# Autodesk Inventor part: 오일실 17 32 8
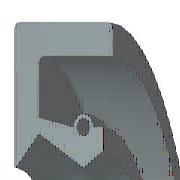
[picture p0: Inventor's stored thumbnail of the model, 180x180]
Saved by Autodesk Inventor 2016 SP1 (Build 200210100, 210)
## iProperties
IsCustomPart: 1
Created: 2012-02
Part Number: 오일실 17 32 8
Material: 고무
Description: 오일-실
Document SubType Name: Modeling
Standard: KS B 2804
Designer: mduedu
Standards Organization: KS
Language: ko-KR
Size Designation: D - 17 32 8
Categories: <MemberInstance><Categories><Category DisplayName="샤프트 부품" InternalName="7f7aeb1f-a693-4053-b835-cee3144e0d98" Mnemonic="SHFT"><Category DisplayName="실링" Intern
Density: 0.93 g/cm^3
Appearance: 고무 - 검은색 - 버전 1.1
Author: mduedu
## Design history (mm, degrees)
revolve "본체" stored, may be unused: angle "d17" = 90 deg
revolve "스프링1" stored, may be unused: angle "d18" = 90 deg
body "Solid1"
sketch "스케치1"
  geometry: L1 (0, 16)-(8, 16); L2 (8, 14.25)-(1.75, 14.25); L3 (1.75, 10.25)-(4.9, 8.5); L4 (4.9, 8.5)-(0, 8.5); L5 (0, 0)-(9.586, 0) reference; L6 (4.9, 8.5)-(6.3, 9.375); L7 (0, 18)-(0, -3) reference; L8 (-1.941, 0)-(11.507, 0) reference; L9 (4.2, 10.6)-(1.75, 11.21); L10 (1.75, 11.21)-(1.75, 14.25); L11 (0, 16)-(0, 8.588); L12 (4.9, 8.5)-(0, 8.5); L13 (1.75, 10.25)-(0.152, 8.528); L14 (8, 16)-(8, 14.25); L15 (5.6, 10.6)-(6.3, 10.6); L16 (6.3, 10.6)-(6.3, 9.375); C1 r 0.455 at (4.9, 10.6); A1 r 0.7 centre (4.9, 10.6) between (5.6, 10.6) and (4.2, 10.6); A2 r 0.088 centre (0.088, 8.588) between (0, 8.588) and (0.152, 8.528); 1 further point
  constraints: 28 end point, 5 horizontal alignment, 5 point on line, 4 point on circle, 4 vertical alignment, 3 centre point, 3 tangent, 2 collinear, 2 horizontal, 2 perpendicular, 1 coincident, 1 parallel
  dimensions: "d0" = 32 diameter of L1 L5 (= SD2); "d1" = 1.75 distance of L1.end L2.start (= SD); "d2" = 0.91 diameter of C1 (= SPDI); "d3" = 1.4 diameter of A1 (= SPDA); "d4" = 17 diameter of L3.end L5 (= NND); "d5" = 20.5 diameter of L3.start L5 (= TKDM); "d7" = 22.42 diameter of L9.end L5 (= TKDM + 0.24 x SWDT); "d8" = 1.75 distance between parallel lines of L11 L10 (= SD); "d9" = 4.9 distance from line of L11 C1.centre (= SPDST); "d10" = 21.2 diameter of C1.centre L5 (= HLDM); "d11" = 0.0875 radius of A2 (= 0.25 x LAB); "d12" = 6.3 distance between parallel lines of L11 L16 (= SDI); "d13" = 18.75 diameter of L6.end L5 (= ABDM); "d14" = 8 distance from line of L11 L1.end (= SWDT)
fillet "모깎기1" dims "d6" = 0.3 (= RR)
other parameters: "SD2" = 32 [user parameter; used in 1 equation term], "SWDT" = 8 [user parameter; used in 2 equation terms], "RR" = 0.3 [user parameter; used in 1 equation term], "SD" = 1.75 [user parameter; used in 2 equation terms], "NND" = 17 [user parameter; used in 1 equation term], "SPDA" = 1.4 [user parameter; used in 1 equation term], "SPDI" = 0.91 [user parameter; used in 1 equation term], "TKDM" = 20.5 [user parameter; used in 2 equation terms], "HLDM" = 21.2 [user parameter; used in 1 equation term], "ABDM" = 18.75 [user parameter; used in 1 equation term], "SDI" = 6.3 [user parameter; used in 1 equation term], "SPDST" = 4.9 [user parameter; used in 1 equation term], "LAB" = 0.35 [user parameter; used in 1 equation term], "d15" = 0, "d16" = 0, "d19" = 0
